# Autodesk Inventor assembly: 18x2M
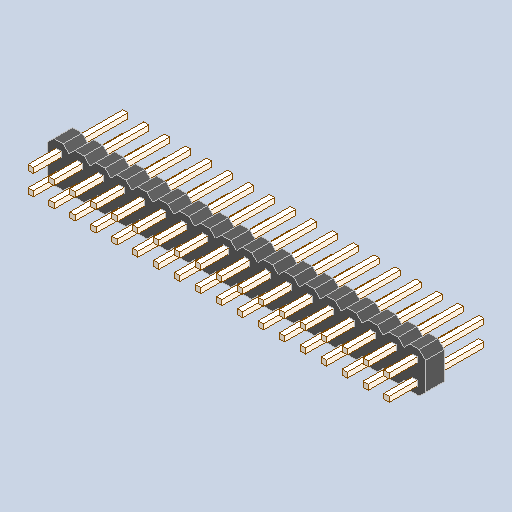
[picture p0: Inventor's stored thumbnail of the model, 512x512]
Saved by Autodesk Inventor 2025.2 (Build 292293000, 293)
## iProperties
Created: 2025-04
Part Number: 18x2M
Description: PART--DESC
Document SubType Name: Assembly
Designer: BennF
Author: BennF
Revision Number: NONE
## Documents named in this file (3)
- C:\Users\BennF\Nextcloud\Benutzer\CNC JarBeRi\existing parts\Electronics\RepRap A4988 Shied (USE WITHOUT ARDUINO)\reprap-a4988-1.snapshot.1\RepRap\RepRap\18x2M.iam
- C:\Users\BennF\Nextcloud\Benutzer\CNC JarBeRi\existing parts\Electronics\RepRap A4988 Shied (USE WITHOUT ARDUINO)\reprap-a4988-1.snapshot.1\RepRap\RepRap\18x2M Geometry.ipt
- C:\Users\BennF\Nextcloud\Benutzer\CNC JarBeRi\existing parts\Electronics\RepRap A4988 Shied (USE WITHOUT ARDUINO)\reprap-a4988-1.snapshot.1\RepRap\RepRap\Pin19.ipt
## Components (2 placed, 2 different names)
1. 18x2M Geometry
2. Pin19
